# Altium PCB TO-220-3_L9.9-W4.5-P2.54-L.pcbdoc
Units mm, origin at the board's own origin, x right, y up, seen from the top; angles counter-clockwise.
Board outline 22.68 x 17.26 mm, 2 copper layers (Top Layer, Bottom Layer), stack 0 mm thick; 1 components, 0 nets, 3 pads, 0 vias.
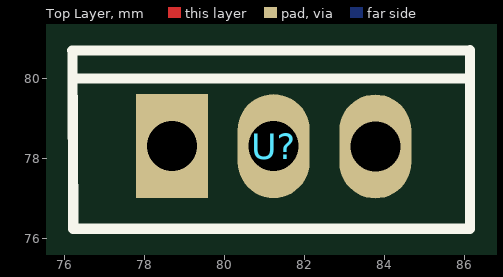
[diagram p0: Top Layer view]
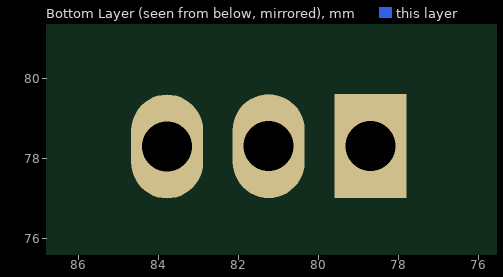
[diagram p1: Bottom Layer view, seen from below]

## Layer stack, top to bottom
Top Layer: signal copper (thickness not stored)
Bottom Layer: signal copper (thickness not stored)

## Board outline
92.535,69.85 69.85,69.85 69.85,87.11 92.535,87.11

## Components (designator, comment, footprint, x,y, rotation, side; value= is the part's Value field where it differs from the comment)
U? "" TO-220-3_L9.9-W4.5-P2.54-L 81.235,78.295 r0 top

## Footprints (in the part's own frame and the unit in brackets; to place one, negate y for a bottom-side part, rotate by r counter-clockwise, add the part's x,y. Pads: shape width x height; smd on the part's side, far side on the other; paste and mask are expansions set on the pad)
TO-220-3_L9.9-W4.5-P2.54-L [mm]
  rect 1.8x2.6 hole 1.25: 1(-2.54,0.005)
  oval 1.8x2.6 hole 1.25: 2(0,0.005) 3(2.54,-0.005)
  silkscreen extent -5.03,-2.06 4.91,2.4

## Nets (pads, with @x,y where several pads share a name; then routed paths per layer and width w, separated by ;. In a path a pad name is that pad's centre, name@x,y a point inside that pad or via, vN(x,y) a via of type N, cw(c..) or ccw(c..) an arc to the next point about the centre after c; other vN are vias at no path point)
pads on no net: U?.1 U?.2 U?.3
